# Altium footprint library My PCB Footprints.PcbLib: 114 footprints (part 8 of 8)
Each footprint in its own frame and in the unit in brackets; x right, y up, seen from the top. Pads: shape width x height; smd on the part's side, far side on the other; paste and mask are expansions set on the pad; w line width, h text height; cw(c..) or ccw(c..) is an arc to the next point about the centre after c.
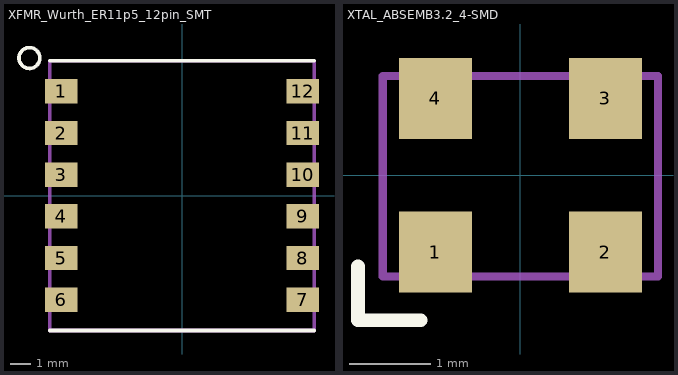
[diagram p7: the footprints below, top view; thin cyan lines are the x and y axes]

## XFMR_Wurth_ER11p5_12pin_SMT [mm] "Recommended land pattern for Wurth ER11p5 - SMT"
height 6.35
pads (12):
  rect 1.57x1.17 smd: 1(-5.79,5) 2(-5.79,3) 3(-5.79,1) 4(-5.79,-1) 5(-5.79,-3) 6(-5.79,-5) 7(5.79,-5) 8(5.79,-3) 9(5.79,-1) 10(5.79,1) 11(5.79,3) 12(5.79,5)
Top Overlay:
  circle w0.178: c-7.325,6.6 r0.5
  lines w0.178: -6.35,-6.475 0,-6.475 6.35,-6.475 ; -6.35,6.475 0,6.475 6.35,6.475
Mechanical 5:
  text ".designator" at -1,-0.5 h1.52
Mechanical 13:
  lines w0.178: -6.35,-6.475 6.35,-6.475 6.35,6.475 -6.35,6.475 -6.35,-6.475
3D body: height 6.35, standoff 0, extent -6.35,-6.475 6.35,6.475
3D body: height 6.35, standoff 6.35, extent -3.861,4.239 -2.339,5.761

## XTAL_ABSEMB3.2_4-SMD [mm] "Abracon recommended land pattern"
height 0.9
pads (4):
  rect 0.9x1 smd: 1(-1.05,-0.95) 2(1.05,-0.95) 3(1.05,0.95) 4(-1.05,0.95)
Top Overlay:
  lines w0.17: -2.006,-1.125 -2.006,-1.791 -1.231,-1.791
Mechanical 5:
  circle w0.1: c-1.131,-0.893 r0.2
  lines w0.1: -1.7,-1.25 -1.7,1.225 1.7,1.225 1.7,-1.25 -1.7,-1.25
  text ".Designator" at -0.05,-0.05 h0.7
3D body: height 0.91, standoff 0.5, extent -1.337,-0.937 -1.063,-0.663
3D body: height 0.9, standoff 0, extent -1.7,-1.249 1.7,1.225
3D body: height 0.9, standoff 0.89, extent -1.699,-1.274 1.7,1.225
